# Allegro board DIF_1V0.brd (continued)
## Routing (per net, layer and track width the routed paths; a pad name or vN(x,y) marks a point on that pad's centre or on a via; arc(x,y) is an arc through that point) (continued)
/BUTTON_LOW: length 3
  TOP w0.152: R7.1 105.94,9.55 SW1.1
CCLK: length 22.1
  TOP w0.152: U5.16 v2(87.71,37.95) ; U3.L12 v1(90.62,54.25)
  ART2 w0.152: v1(90.62,54.25) 90.93,53.93 90.93,41.35 87.71,38.13 v2(87.71,37.95)
DONE: length 13.1
  TOP w0.152: v2(105.51,56.08) 104.8,55.37 D9.2 104.72,55.19 94.64,55.19 94.15,55.68 U3.G11
  BOTTOM w0.152: R44.1 104.8,56.08 v2(105.51,56.08)
FIFOADR0: length 34.1
  TOP w0.152: U12.44 67.61,22.85 67.61,24.49 66.95,25.15 66.95,32.92 75.01,40.97 v2(75.01,42.44) ; U3.V18 v1(82.69,48.25)
  ART2 w0.152: v1(82.69,48.25) 82.14,47.7 80.11,47.7 75.01,42.6 v2(75.01,42.44)
FIFOADR1: length 30.6
  TOP w0.152: U12.45 67.02,24.24 66.47,24.79 66.47,33.43 73.51,40.46 73.51,42.11 76.56,45.16 79.63,45.16 80.15,45.68 U3.AA21
FLASH_CS_B: length 29.9
  TOP w0.152: U3.T19 85.72,47.14 v2(85.75,47.14) ; v2(94.82,26.19) 95.33,25.68 U5.7
  BOTTOM w0.152: v2(94.82,26.19) 94.18,26.82 R37.1 94.69,27.51 94.69,36.86 92.15,39.4 89.18,39.4 85.57,43 85.57,44.48 85.29,44.75 85.29,46.69 v2(85.75,47.14)
FLASH_DQ0: length 11.2
  TOP w0.152: U3.P22 87.15,43.73 88.98,41.91 U5.15
FLASH_DQ1: length 27
  TOP w0.152: U3.R22 v1(86.15,44.04) ; v2(92.68,41.25) 97.23,36.7 97.23,32.8 96.6,32.16 96.6,28.25 96.7,28.15 96.7,27.73 96.6,27.63 U5.8
  BOTTOM w0.152: v2(92.68,41.25) 88.94,41.25 v1(86.15,44.04)
FLASH_DQ2: length 17.7
  TOP w0.152: v2(95.73,35.99) 96.6,35.13 U5.9 ; v2(88.39,41) 86.64,42.75 86.64,45.21 87.14,45.71 U3.P21
  BOTTOM w0.152: v2(88.39,41) 89.08,40.31 92.25,40.31 R36.1 95.73,36.83 v2(95.73,35.99)
FLASH_DQ3: length 23.3
  TOP w0.152: U5.1 87.71,25.81 86.46,27.05 R35.1 86.72,28.12 86.72,39.6 85.67,40.64 85.67,45.24 86.15,45.71 U3.R21
FPGA_LED1: length 33
  TOP w0.152: TP1.1 117.2,24.38 107.14,34.44 107.14,41.58 102.01,46.71 U3.A20
  TOP w0.203: R11.1 TP1.1
FPGA_LED2: length 29.8
  TOP w0.152: U3.C22 98.15,44.42 106.35,36.22 106.35,32.97 115.11,24.21 TP2.1
  TOP w0.203: R12.1 TP2.1
FPGA_LED3: length 30.4
  TOP w0.152: U3.D21 97.15,45.65 97.66,45.14 97.66,43.92 105.31,36.27 105.31,32.44 113.03,24.71 TP3.1
  TOP w0.203: R13.1 TP3.1
FPGA_LED4: length 29.9
  TOP w0.152: U3.E21 96.15,45.68 96.67,45.16 96.67,43.87 104.01,36.53 104.01,31.7 110.95,24.77 TP4.1
  TOP w0.203: R14.1 TP4.1
FPGA_LED5: length 28.1
  TOP w0.152: TP5.1 108.86,24.66 102.49,31.04 102.49,37.03 96.15,43.37 U3.E22
  TOP w0.203: R15.1 TP5.1
FPGA_LED6: length 29.6
  TOP w0.152: U3.F20 95.63,46.23 95.63,42.95 101.12,37.47 101.12,30.78 104.01,27.89 104.01,27.86 106.78,25.1 TP6.1
  TOP w0.203: R16.1 TP6.1
FPGA_LED7: length 28.6
  TOP w0.152: TP7.1 104.7,25.55 102.08,28.17 101.4,28.17 99.8,29.77 99.8,37.82 94.67,42.95 94.67,44.96 94.15,45.47 U3.G21
  TOP w0.203: R17.1 TP7.1
FPGA_LED8: length 26.3
  TOP w0.152: U3.G22 94.15,42.35 98.37,38.13 98.37,29.44 102.62,25.2 TP8.1
  TOP w0.203: R18.1 TP8.1
GTP0_RD+: length 32.3
  TOP w0.152: 106.5,57.43 C126.1 107.07,57.43 107.89,58.26 121.77,58.26 132.17,47.86 132.17,47.28 131.93,47.04 DU1.13
GTP0_RD-: length 32.7
  TOP w0.152: DU1.12 132.72,47.07 132.47,47.31 132.47,47.99 121.9,58.56 107.89,58.56 107.24,59.21 C120.1 106.5,59.21
GTP0_TD+: length 33.8
  TOP w0.152: DU1.18 127.91,47.07 127.67,47.31 127.67,47.99 123.74,51.92 109.7,51.92 v2(109.41,52.21) ; v2(107.35,60.25) 107.35,60.85 R67.2 107.8,61.29 C127.2
  BOTTOM w0.152: v2(109.41,52.21) 107.01,54.61 107.01,59.9 v2(107.35,60.25)
GTP0_TD-: length 34.2
  TOP w0.152: C133.2 105.77,62.61 105.94,62.43 105.94,61.32 R67.1 106.41,60.85 v2(106.41,60.25) ; v2(108.47,52.21) 109.07,51.61 123.61,51.61 127.37,47.86 127.37,47.31 127.13,47.07 DU1.19
  BOTTOM w0.152: v2(106.41,60.25) 106.71,59.96 106.71,53.98 v2(108.47,52.21)
GTP0_TX_DETECT: length 20.9
  TOP w0.152: D13.1 117.88,43.33 v2(119.86,41.35)
  TOP w0.203: v2(130.68,36.02) 130.68,37.74 DU1.6
  ART2 w0.152: v2(130.68,36.02) 130.07,35.41 123.9,35.41 119.86,39.45 v2(119.86,41.35)
  BOTTOM w0.203: DR3.1 v2(130.68,36.02)
IN_DATA_1+: length 29.2
  TOP w0.152: U8.6 32.39,7.45 v2(32.84,7.9)
  TOP w0.203: U8.6 32.36,7.27 32.36,8.72 39.22,15.57 45.8,15.57 49.38,19.15 U11.2 ; U8.18 v2(33.14,5.16)
  BOTTOM w0.152: v2(33.14,5.16) 32.84,5.46 v2(32.84,7.9)
IN_DATA_1-: length 24.3
  TOP w0.152: U8.7 32.64,6.49 U8.19
  TOP w0.203: U8.7 33.39,8.09 40.21,14.91 46.58,14.91 49.56,17.88 U11.1
IN_DATA_5+: length 26.7
  TOP w0.152: v2(49.3,11.1) 47.08,8.88 U9.2 ; v2(52.02,5.16) 51.83,5.34 U9.14 ; v2(51.21,23.63) U11.6
  BOTTOM w0.152: v2(52.02,5.16) 52.02,8.38 v2(49.3,11.1) 49.3,21.73 v2(51.21,23.63)
IN_DATA_5-: length 26.5
  TOP w0.152: v2(49.3,10.24) 47.58,8.52 U9.3 ; U11.7 50.62,24.92 v2(50.62,24.91) ; v2(51.13,5.13) 51.33,5.33 U9.15
  ART2 w0.152: v2(49.3,10.24) 49.81,10.74 49.81,24.09 v2(50.62,24.91)
  BOTTOM w0.152: v2(51.13,5.13) 51.13,8.41 v2(49.3,10.24)
IN_DATA_6+: length 34.3
  TOP w0.152: v2(46.53,25.5) U11.10 ; U9.23 47.33,5.24 v2(47.13,5.04) ; v2(47.13,13.84) 47.64,14.35 48.31,14.35 52.08,10.58 U9.11
  BOTTOM w0.152: v2(47.13,5.04) v2(47.13,13.84) 47.13,24.9 v2(46.53,25.5)
IN_DATA_6-: length 34.4
  TOP w0.152: U9.22 47.83,5.2 v2(48.03,5) ; v2(48.01,13.74) 51.58,10.17 U9.10 ; v2(46.81,26.75) 44.04,26.75 U11.9
  BOTTOM w0.152: v2(46.81,26.75) 48.41,25.15 48.41,14.15 v2(48.01,13.74) 48.03,13.72 v2(48.03,5)
IN_MONITOR: length 31.3
  TOP w0.152: U3.K2 v1(91.62,65.18)
  BOTTOM w0.152: v1(91.62,65.18) 91.62,72.75 106.17,87.3 R121.1
IN_TX_HV: length 53.9
  TOP w0.152: U6.4 33,79.67 42.9,69.77 60.55,69.77 67.94,62.38 75.67,62.38 76.34,61.71 U3.AB5
INIT_B: length 16.3
  TOP w0.152: v2(72.62,58.5) 71.96,58.5 D10.1 ; U3.U12 v2(83.69,55.17)
  BOTTOM w0.152: v2(83.69,55.17) 77.47,55.17 74.52,58.12 73.05,58.12 72.67,58.5 v2(72.62,58.5) 72.57,58.45 72.57,58.01 R45.1
IO_PRE_2.5_1: length 31.4
  TOP w0.102: U3.A1 99.86,65.71 99.75,65.81 99.75,70.97 115.85,87.06 115.85,87.95 115.96,88.06 v1(115.96,88.35)
  BOTTOM w0.102: R137.1 115.96,89.34 v1(115.96,88.35)
IO_PRE_2.5_2: length 31.4
  TOP w0.102: U3.B1 99.45,65.71 99.55,65.81 99.55,71.05 115.65,87.15 115.65,87.95 115.53,88.06 v1(115.53,88.35)
  BOTTOM w0.102: v1(115.53,88.35) 115.53,89.19 R139.1
IO_PRE_2.5_3: length 32.2
  TOP w0.102: U3.C2 98.45,64.71 98.55,64.81 98.55,72.04 114.25,87.74 114.25,88.65 113.64,89.26 R133.2
IO_PRE_2.5_4: length 32.2
  TOP w0.102: R135.2 115.06,89.26 114.45,88.65 114.45,87.66 98.75,71.96 98.75,64.81 98.86,64.71 U3.B2
IO_PRE_2.5_5: length 31.1
  TOP w0.102: v1(111.61,87.85) 111.61,87.56 111.72,87.44 111.72,86.42 96.55,71.25 96.55,65.81 96.45,65.71 U3.E1
  BOTTOM w0.102: R129.1 111.12,89.24 111.73,88.63 111.73,88.14 111.61,88.01 v1(111.61,87.85)
IO_PRE_2.5_6: length 31.1
  TOP w0.102: U3.D1 96.86,65.71 96.75,65.81 96.75,71.17 111.93,86.34 111.93,87.44 112.04,87.56 v1(112.04,87.85)
  BOTTOM w0.102: v1(112.04,87.85) 112.04,88.04 111.94,88.14 111.94,88.68 112.52,89.26 R131.1
IO_PRE_2.5_7: length 40.1
  TOP w0.152: U3.G3 94.15,63.72 v1(94.61,64.19)
  BOTTOM w0.152: v1(94.61,64.19) 94.64,64.19 95.17,64.72 95.17,69.32 111.33,85.47 116.76,85.47 120.14,88.85 R143.2
IO_PRE_2.5_8: length 41.9
  TOP w0.152: v1(95.63,63.17) 95.17,62.71 U3.F4 ; R149.1 v2(123.98,88.62)
  ART2 w0.152: v2(123.98,88.62) 112.7,77.34 107.77,77.34 96.19,65.76 96.19,63.73 v1(95.63,63.17)
IO_PRE_2.5_9: length 42.3
  TOP w0.152: U3.E2 96.18,64.71 v1(96.67,65.2)
  BOTTOM w0.152: v1(96.67,65.2) 96.67,68.55 111.02,82.91 119.79,82.91 125.22,88.34 R151.2
IO_PRE_2.5_10: length 43.9
  TOP w0.152: v1(96.62,64.16) 96.17,63.71 U3.E3 ; R153.1 v2(126.49,88.01)
  BOTTOM w0.152: v2(126.49,88.01) 119.2,80.72 110.26,80.72 97.18,67.64 97.18,64.67 96.67,64.16 v1(96.62,64.16)
IO_PRE_2.5_11: length 43.6
  TOP w0.152: U3.D2 97.15,64.72 v1(97.64,65.2)
  BOTTOM w0.152: R155.2 127.76,87.17 118.9,78.31 109.04,78.31 97.64,66.9 v1(97.64,65.2)
IO_PRE_3.3_1: length 31.8
  TOP w0.152: U3.R2 86.15,64.72 85.6,65.28 85.6,72.03 69.09,88.54 R160.2
IO_PRE_3.3_2: length 34.1
  TOP w0.152: v1(85.62,64.24) 86.15,63.71 U3.R3
  BOTTOM w0.152: v1(85.62,64.24) 85.62,72.39 R158.1
IO_PRE_3.3_3: length 34.8
  TOP w0.152: U3.R4 86.15,62.74 v1(85.65,63.25) ; R156.2 v2(66.55,88.16)
  ART2 w0.152: v2(66.55,88.16) 85.12,69.6 85.12,63.75 85.62,63.25 v1(85.65,63.25)
IO_PRE_3.3_4: length 36.6
  TOP w0.152: v1(84.66,63.17) 85.12,62.71 U3.T4
  ART2 w0.152: v1(84.66,63.17) 84.63,63.17 84.1,63.7 82.6,63.7 81.64,64.67 81.64,69.85 65.28,86.21 v2(65.28,88.27)
  BOTTOM w0.152: R154.1 v2(65.28,88.27)
IO_PRE_3.3_5: length 34.3
  TOP w0.152: R152.2 64.01,88.62 66.4,86.23 69.49,86.23 85.15,70.58 U3.T1
IO_PRE_3.3_6: length 38
  TOP w0.152: U3.T3 85.15,63.72 v1(84.66,64.21)
  BOTTOM w0.152: R150.1 62.74,89.46 67.41,84.79 71.12,84.79 84.15,71.75 84.15,64.69 84.63,64.21 v1(84.66,64.21)
IO_PRE_3.3_7: length 35
  TOP w0.102: 84.15,68.17 U3.U1
  TOP w0.152: R148.2 61.47,89.26 66.52,84.2 69.75,84.2 84.15,69.8 84.15,68.17
IO_PRE_3.3_8: length 39
  TOP w0.152: U3.U3 84.12,63.71 v1(83.64,64.19)
  BOTTOM w0.152: R146.1 60.2,89.56 67.49,82.27 71.7,82.27 83.64,70.33 v1(83.64,64.19)
IO_PRE_3.3_9: length 34
  TOP w0.152: R144.2 v2(58.93,88.29) ; U3.Y1 81.15,67.87 78.71,70.31 v2(76.91,70.31)
  ART2 w0.152: v2(76.91,70.31) v2(58.93,88.29)
IO_PRE_3.3_10: length 41.8
  TOP w0.152: U3.V3 v1(82.68,64.19)
  BOTTOM w0.152: v1(82.68,64.19) 82.68,68.99 71.58,80.09 65.68,80.09 55.5,90.27 R138.1
IO_PRE_3.3_11: length 54.3
  TOP w0.152: R111.2 38.61,89.15 52.63,75.13 64.52,75.13 71.12,68.53 79.63,68.53 80.67,67.49 80.67,65.2 81.15,64.72 U3.Y2
IO_PRE_3.3_12: length 54.1
  TOP w0.152: U3.V5 83.15,61.71 v1(82.65,62.2)
  ART2 w0.152: v1(76.17,64.46) 78.95,61.67 82.19,61.67 82.65,62.13 v1(82.65,62.2)
  BOTTOM w0.152: R118.1 42.42,89.84 57.15,75.11 66.83,75.11 76.17,65.77 v1(76.17,64.46)
IO_PRE_3.3_13: length 48.2
  TOP w0.152: U3.V4 83.14,62.71 v1(82.63,63.22)
  BOTTOM w0.152: R130.1 50.04,88.62 61.29,77.37 67.79,77.37 74.12,71.04 79.3,71.04 82.37,67.97 82.37,64.35 82.35,64.32 82.35,64.05 82.37,64.02 82.37,63.91 82.63,63.65 v1(82.63,63.22)
IO_PRE_3.3_14: length 44.5
  TOP w0.152: R132.2 51.31,89.15 58.06,82.4 69.39,82.4 82.65,69.14 82.65,65.21 U3.V2
IO_PRE_3.3_15: length 42.7
  TOP w0.152: U3.W1 82.35,65.9 82.35,68.28 78.74,71.88 v2(77.29,71.88)
  BOTTOM w0.152: R134.1 52.58,88.29 62.15,78.71 68.99,78.71 75.82,71.88 v2(77.29,71.88)
IO_SMA1: length 52.3
  TOP w0.152: U3.B21 99.59,46.15 v2(101.7,46.15) ; R19.2 125.68,21.79 108.08,39.4 v2(108.08,41.4)
  BOTTOM w0.152: v2(108.08,41.4) 106.45,41.4 v2(101.7,46.15)
IO_SMA2: length 48
  TOP w0.152: v2(101.04,45.69) 101.03,45.71 U3.A21 ; v2(109.45,38.81) 119.81,28.45 137.9,28.45 139.57,30.12 R26.2
  BOTTOM w0.152: v2(109.45,38.81) 107.92,38.81 v2(101.04,45.69)
IO_SMA3: length 44.1
  TOP w0.152: R30.2 v2(138.94,44.45) ; U3.B15 99.19,51.71 99.69,51.21 105.36,51.21 v2(105.51,51.05)
  ART2 w0.152: v2(105.51,51.05) 111.38,45.19 135.59,45.19 136.32,44.45 v2(138.94,44.45)
IO_SMA4: length 49.1
  TOP w0.102: v1(94.72,53.16) 94.17,53.71 U3.G13 ; v2(137.72,64.21) R28.2
  ART2 w0.102: v1(94.72,53.16) 94.72,53.24 95.2,53.72 124.51,53.72 135,64.21 v2(137.72,64.21)
IO_SMA5: length 45.8
  TOP w0.102: v1(94.67,51.21) 94.16,51.71 U3.G15 ; R32.2 138.23,53.52 v2(137.72,53.52)
  ART2 w0.102: v1(94.67,51.21) 94.69,51.21 96.16,52.68 113.13,52.68 113.69,52.12 130.56,52.12 131.8,53.37 137.57,53.37 v2(137.72,53.52)
M2: length 31
  TOP w0.152: J8.2 56.74,62.31 59.03,60.02 72.29,60.02 76.12,56.18 81.38,56.18 81.72,56.53 81.72,56.89 81.97,57.14 83.58,57.14 U3.U9
Net_18: length 0.7
  TOP w0.152: 87.15,49.71 v1(86.69,49.25)
Net_41: length 0.7
  TOP w0.152: 92.15,64.71 92.15,64.72 v1(92.61,65.18)
Net_42: length 0.7
  TOP w0.152: 90.15,63.71 v1(90.65,64.21)
Net_44: length 0.7
  TOP w0.152: v1(93.62,64.19) 93.15,63.71 93.15,63.71
Net_45: length 0.6
  TOP w0.152: 93.15,62.71 93.16,62.71 v1(93.6,63.14)
Net_46: length 0.7
  TOP w0.152: 95.15,63.71 95.18,63.71 v1(95.66,64.19)
Net_47: length 0.7
  TOP w0.152: v1(93.68,62.23) 93.16,61.71 93.15,61.71
Net_48: length 0.7
  TOP w0.152: v1(94.61,63.17) 94.16,62.71 94.15,62.71
OUT_CK_5N_1: length 3.5
  TOP w0.127: R81.2 84.68,88.58 84.71,88.56 R69.1 84.71,86.44 R70.1
OUT_CK_5P_1: length 3.6
  TOP w0.127: R68.2 83.19,86.33 R69.2 83.19,88.56 83.21,88.58 R79.2
OUT_CK_40N_1: length 3.6
  BOTTOM w0.127: R108.1 87.27,88.01 R115.1
  BOTTOM w0.152: R108.1 87.15,88.14 R97.1
OUT_CK_40P_1: length 3.6
  BOTTOM w0.127: R108.2 85.7,86.44 R95.2
  BOTTOM w0.152: R84.1 85.75,88.11 R108.2
OUT_DATA_2+: length 48.2
  TOP w0.203: U8.2 30.39,8.8 24.56,14.63 24.56,23.29 25.63,24.36 U10.2 31.04,24.36 v2(31.09,24.31) ; U8.14 35.14,4.89 v2(35.33,4.7)
  BOTTOM w0.203: v2(35.33,4.7) 34.19,5.84 34.19,21.21 v2(31.09,24.31)
OUT_DATA_2-: length 45.4
  TOP w0.203: U8.3 30.89,8.8 24.94,14.75 24.94,22.56 25.48,23.09 U10.3 31.22,23.09 v2(31.27,23.04) ; U8.15 34.64,4.9 v2(34.44,4.7)
  BOTTOM w0.203: v2(31.27,23.04) 33.63,20.68 33.63,5.51 v2(34.44,4.7)
OUT_DATA_3+: length 30.9
  TOP w0.152: v2(35.38,8.51) 35.38,7.25 U8.11
  TOP w0.203: U8.23 30.64,5.12 v2(30.56,5.03) ; U10.6 30.07,19.28 30.56,18.8 v2(30.56,18.68)
  ART2 w0.152: v2(30.56,18.68) 34.06,15.18 34.06,9.25 34.69,8.62 35.28,8.62 v2(35.38,8.51)
  BOTTOM w0.203: v2(30.56,18.68) v2(30.56,5.03)
OUT_DATA_3-: length 34.7
  TOP w0.152: v2(35.38,9.3) 35.38,9.28 34.85,8.74 34.85,7.28 U8.10
  TOP w0.203: v2(31.22,5.08) 31.14,5.15 U8.22 ; v2(31.22,20.45) 28.45,20.45 U10.5
  ART2 w0.152: v2(31.22,20.45) 31.72,20.45 35.38,16.79 v2(35.38,9.3)
  BOTTOM w0.203: v2(31.22,20.45) v2(31.22,5.08)
OUT_DATA_4+: length 20.2
  TOP w0.152: U10.10 35.56,18.03 v2(38.18,18.03) ; v2(49.08,8.31) U9.6 49.83,6.49 U9.18
  ART2 w0.152: v2(38.18,18.03) 39.35,18.03 v2(49.08,8.31)
OUT_DATA_4-: length 23.4
  TOP w0.152: U9.7 50.04,7.28 50.04,7.29 v2(49.68,7.65) ; v2(38.15,19.28) U10.11 ; U9.19 v2(49.33,5.18)
  ART2 w0.152: v2(38.15,19.28) 38.83,19.28 49.68,8.43 v2(49.68,7.65)
  BOTTOM w0.152: v2(49.33,5.18) 49.68,5.53 v2(49.68,7.65)
OUT_RAZ_CHN_N_1: length 4.7
  TOP w0.102: 94.21,87.93 94.21,87.93 94.11,87.82 94.11,86.94 R90.1 ; 94.21,87.93 R85.1 ; 94.21,87.93 94.11,88.04 94.11,88.65 94.72,89.26 R93.2
OUT_RAZ_CHN_P_1: length 4.9
  TOP w0.102: R102.2 93.24,89.26 93.9,88.6 93.9,88.04 93.8,87.93 ; R85.2 93.8,87.93 ; 93.8,87.93 93.9,87.83 93.9,87 93.19,86.28 R82.2
OUT_RX_HV: length 55.4
  TOP w0.152: U6.3 33.23,80.94 42.65,71.53 59.79,71.53 68.3,63.02 76.71,63.02 77.47,62.26 79.63,62.26 80.15,61.73 U3.AA5
OUT_TRIG_EXT_N_1: length 3.5
  BOTTOM w0.127: R76.1 92.38,86.41 R75.1 92.3,88.09 R101.1
OUT_TRIG_EXT_P_1: length 3.6
  BOTTOM w0.127: R74.2 90.73,86.36 90.86,86.49 R75.2 90.91,88.06 R89.1
OUT_VAL_EVT_N_1: length 4.2
  TOP w0.102: R88.2 89.84,89.74 89.2,89.1 89.2,88.57 89.81,87.96 R72.1
  TOP w0.127: R72.1 89.89,86.44 R73.1
OUT_VAL_EVT_P_1: length 4.1
  TOP w0.102: R72.2 89,88.6 89,89.08 88.37,89.71 R98.2
  TOP w0.127: R72.2 88.37,86.39 R71.2
PROGRAM_B: length 44.1
  TOP w0.152: v2(108.08,34.49) 108.13,34.54 R43.1 110.72,34.54 SW2.2 ; U3.N12 88.15,54.7 v1(87.63,54.18)
  BOTTOM w0.152: v2(108.08,34.49) 108.03,34.54 104.8,34.54 96.75,42.6 89.46,42.6 88.14,43.92 88.14,53.67 v1(87.63,54.18)
REFCLK+: length 6
  BOTTOM w0.102: C1.1 112.29,61.04 R1.1 113.77,61.52 114.05,61.8 116.36,61.8 116.56,61.59 O1.4
REFCLK-: length 5.8
  BOTTOM w0.102: O1.5 116.56,62.23 116.33,62 114.02,62 113.77,62.26 R1.2 112.62,62.56 C5.1
RESET#: length 32.3
  TOP w0.203: U12.49 64.47,22.8 v2(64.47,21.29)
  ART2 w0.203: U15.2 85.98,17.42 68.33,17.42 v2(64.47,21.29)
  BOTTOM w0.203: C115.1 87.62,21.62 R65.1 87.68,19.13 U15.2
RX_VCCP_0: length 11.5
  TOP w0.305: v3(129.9,43.89) 130.33,44.32 DU1.15
  BOTTOM w0.203: C130.1 131.93,46.18 C129.1
  BOTTOM w0.305: C130.1 131.6,45.97 129.9,44.27 v3(129.9,43.89) L5.1 129.18,43.38 C128.1
SCL: length 15.4
  TOP w0.203: v2(73.38,14.3) 73.38,12.92 U12.22 ; v2(75.51,11.46) U14.6 84.3,11.89 R63.1
  BOTTOM w0.203: v2(75.51,11.46) 73.38,13.59 v2(73.38,14.3)
SDA: length 13.8
  TOP w0.203: U12.23 74,11.95 75.08,10.87 81.92,10.87 U14.5 83.9,8.89 R64.1
SFP_RS0: length 8.2
  TOP w0.203: DU1.7 131.52,38.96 132.94,40.39 v2(135.69,40.39)
  BOTTOM w0.203: v2(135.69,40.39) 136.35,40.39 DR14.1 136.8,40.79 DR15.1
SFP_RS1: length 8.5
  TOP w0.203: v2(135.69,32.36) 133.12,34.92 DU1.9
  BOTTOM w0.203: DR12.1 DR13.1 v2(135.69,32.36)
TRG_EXT: length 14.3
  TOP w0.152: R22.2 113.45,53.71 U3.A13
TX_VCCP_0: length 13.3
  TOP w0.305: DU1.16 129.51,47.24 128.65,48.11 v3(128.65,48.67)
  BOTTOM w0.203: C122.1 L4.1
  BOTTOM w0.305: C121.1 126.19,52.71 C123.1 129.41,50.5 L4.1 129.54,49.56 v3(128.65,48.67)
USB_CLKOUT: length 44.1
  TOP w0.152: U3.Y18 v1(80.69,48.25)
  BOTTOM w0.152: R52.1 60.53,19.53 60.53,34.14 69.72,43.33 70.94,43.33 75.86,48.25 v1(80.69,48.25)
USB_FD0: length 34.7
  TOP w0.152: v2(80.39,38.13) 80.39,41.38 82.15,43.14 U3.W22
  TOP w0.203: U12.25 v2(75.27,21.15)
  BOTTOM w0.152: v2(80.39,38.13) 80.39,32.11 75.27,26.99 v2(75.27,21.15)
USB_FD1: length 36.6
  TOP w0.152: U3.T21 85.13,45.71 84.68,45.26 84.68,42.24 83.92,41.48 83.92,32.41 78,26.49 78,21.77 75.91,19.67 U12.26
USB_FD2: length 40.8
  TOP w0.152: U12.27 76.54,18.78 80.04,22.28 80.04,27.66 84.56,32.18 84.56,41.28 v2(84.66,41.38) ; U3.R17 v1(85.69,49.25)
  ART2 w0.152: v1(85.69,49.25) 85.69,49.19 85.14,48.64 85.14,46.43 84.66,45.95 v2(84.66,41.38)
USB_FD3: length 42
  TOP w0.152: U12.28 77.18,18.1 81.36,22.28 81.36,27.61 85.17,31.42 v2(85.17,40.74) ; U3.P16 v1(86.69,50.25)
  ART2 w0.152: v1(86.69,50.25) 86.64,50.25 86.16,49.76 86.16,44.86 85.65,44.35 85.65,41.16 85.23,40.74 v2(85.17,40.74)
USB_FD4: length 29.4
  TOP w0.152: U12.29 77.18,26.99 83.29,33.1 v2(83.29,39.19) ; U3.T18 v1(84.69,48.25)
  ART2 w0.152: v2(83.29,39.19) 83.29,46.51 83.57,46.79 83.95,46.79 84.69,47.53 v1(84.69,48.25)
USB_FD5: length 29.9
  TOP w0.152: v2(82.75,38.79) 82.75,33.22 76.54,27.01 U12.30 ; U3.R18 v1(85.69,48.25)
  BOTTOM w0.152: v2(82.75,38.79) 82.75,40.46 83.69,41.4 83.69,42.27 84.82,43.39 84.82,46.82 85.69,47.69 v1(85.69,48.25)
USB_FD6: length 26.3
  TOP w0.152: U12.31 75.91,27.42 82.25,33.76 82.25,39.98 82.45,40.18 82.45,41.73 83.67,42.95 83.67,45.26 84.11,45.71 U3.U21
USB_FD7: length 29.6
  TOP w0.152: U12.32 75.27,27.98 81.71,34.42 v2(81.71,40.64) ; U3.U18 v1(83.69,48.25)
  BOTTOM w0.152: v1(83.69,48.25) 83.69,48.23 83.16,47.7 83.16,42.09 v2(81.71,40.64)
USB_FD8: length 34.6
  TOP w0.152: U12.52 62.57,24.64 61.72,25.49 61.72,34.65 73.79,46.71 U3.AB20
USB_FD9: length 36.6
  TOP w0.152: U12.53 61.94,24.24 61.16,25.02 61.16,34.77 73.56,47.17 79.55,47.17 80.09,47.71 U3.AA19
USB_FD10: length 38.1
  TOP w0.152: U3.AA18 80.15,48.71 79.65,48.21 73.36,48.21 60.5,35.36 60.5,24.92 61.3,24.12 U12.54
USB_FD11: length 38
  TOP w0.152: U3.AB18 72.89,48.71 59.74,35.56 59.74,25.07 60.67,24.14 U12.55
USB_FD12: length 43.4
  TOP w0.152: v2(67.48,44.36) 59.03,35.92 59.03,25.12 60.03,24.12 U12.56 ; U3.V17 v1(82.69,49.25)
  BOTTOM w0.152: v2(67.48,44.36) 71.81,48.69 82.14,48.69 82.69,49.24 v1(82.69,49.25)
USB_FD13: length 56.7
  TOP w0.152: U3.W17 v1(81.69,49.25) ; U12.1 60.03,18.5 56.62,21.92 56.62,37.72 v2(64.5,45.61)
  BOTTOM w0.152: v2(64.5,45.61) 68.14,49.25 v1(81.69,49.25)
USB_FD14: length 57.9
  TOP w0.152: U3.U17 v1(83.69,49.25) ; v2(64.24,44.22) 57.68,37.67 57.68,22.05 60.67,19.06 U12.2
  ART2 w0.152: v1(83.69,49.25) 83.67,49.25 83.19,49.73 76.5,49.73 72.9,46.13 66.17,46.13 64.26,44.22 v2(64.24,44.22)
USB_FD15: length 58.9
  TOP w0.152: v2(66.65,44.75) 58.39,36.5 58.39,22.68 61.3,19.77 U12.3 ; U3.R16 v1(85.69,50.25)
  ART2 w0.152: v2(66.65,44.75) 67.01,45.11 72.92,45.11 76.53,48.72 83.95,48.72 84.1,48.87 84.1,49.71 84.64,50.25 v1(85.69,50.25)
USB_FLAGA: length 28.2
  TOP w0.152: U12.36 72.73,26.56 80.98,34.8 v2(80.98,41.1) ; U3.V20 v1(82.69,46.25)
  BOTTOM w0.152: v1(82.69,46.25) 82.69,46.24 82.17,45.72 82.17,42.29 v2(80.98,41.1)
USB_FLAGB: length 28.1
  TOP w0.152: v2(79.78,40.67) 79.78,34.49 72.31,27.03 72.31,24.52 72.1,24.31 U12.37 ; U3.W20 v1(81.69,46.25)
  BOTTOM w0.152: v2(79.78,40.67) 79.78,41.53 81.13,42.88 81.13,45.69 81.68,46.25 v1(81.69,46.25)
USB_FLAGC: length 23.7
  TOP w0.152: R55.2 71.48,27.1 79.15,34.77 79.15,41.02 81.69,43.56 81.69,45.29 82.11,45.71 U3.W21
USB_FLAGD/SLCS#: length 33.6
  TOP w0.152: v2(71.98,41.61) 65.13,34.75 65.13,24.74 65.75,24.12 U12.47 ; U3.Y19 v1(80.69,47.25)
  BOTTOM w0.152: v2(71.98,41.61) 76.07,45.69 79.15,45.69 80.69,47.24 v1(80.69,47.25)
USB_IFCLK: length 35.6
  TOP w0.152: U3.Y22 81.15,43.69 78.41,40.94 v2(78.41,39.62)
  TOP w0.203: U12.20 v2(72.1,21.12)
  BOTTOM w0.152: v2(72.1,21.12) 72.1,29.63 78.41,35.94 v2(78.41,39.62)
USB_PKTEND: length 30.7
  TOP w0.152: U3.AB21 75.61,45.71 72.69,42.8 72.69,41.02 65.86,34.19 65.86,24.77 66.38,24.24 U12.46
USB_SLOE: length 23.7
  TOP w0.152: R58.2 69.85,27.03 77.7,34.87 77.7,40.92 80.62,43.84 80.62,45.21 81.12,45.71 U3.Y21
USB_SLRD: length 37.9
  TOP w0.152: v2(77.38,41.69) 79.15,43.47 U3.AB22
  TOP w0.203: U12.8 64.48,19.04 v2(66.42,20.98)
  BOTTOM w0.152: v2(77.38,41.69) 75.87,40.18 75.87,35 66.42,25.55 v2(66.42,20.98)
USB_SLWR: length 41.6
  TOP w0.152: U3.W19 v1(81.69,47.25)
  BOTTOM w0.152: R59.2 65.65,17.49 65.65,37.15 75.64,47.14 79.53,47.14 80.01,47.63 81.31,47.63 v1(81.69,47.25)
USB_WAKEUP: length 29.9
  TOP w0.152: U3.AA20 80.14,46.71 79.63,46.2 74.47,46.2 64.26,35.99 64.26,28.83 63.2,27.76 R56.1
USB_WU2: length 28.3
  TOP w0.152: v2(77.19,43.74) 75.87,42.42 75.87,34.29 R57.1 ; U3.V19 v1(82.69,47.25)
  ART2 w0.152: v1(82.69,47.25) 82.69,47.23 82.14,46.69 80.14,46.69 v2(77.19,43.74)
WU: length 7.1
  TOP w0.203: J13.2 62.28,28.32 62.28,26.21 R56.2 63.2,22.82 U12.51
WU2_S: length 7.2
  TOP w0.203: J14.2 67.49,28.55 67.49,26.01 R57.2 68.29,25.18 U12.43
XTALIN: length 9.9
  TOP w0.203: U12.12 67.02,7.66 Y1.1
  BOTTOM w0.203: C107.2 66.7,7.34 Y1.1
XTALOUT: length 12.5
  TOP w0.203: U12.11 66.38,10.07 62.61,6.3 Y1.2
  BOTTOM w0.203: C106.2 61.95,7.67 Y1.2
N00327: length 5.3
  TOP w0.203: C102.1 32.61,72.14 U6.10
  TOP w0.305: U6.10 32.69,72.06 R48.1
N00500: length 9.5
  TOP w0.305: U6.16 17.73,79.95 R49.2
N00677: length 1.5
  TOP w0.305: R50.2 13.88,84.98 U7.3
N00715: length 5.6
  TOP w0.152: v3(13.11,81.53) 12.88,81.76 12.88,83.24 12.38,83.73 U7.4
  TOP w0.305: U7.4 11.93,85.1 R51.2
  BOTTOM w0.305: C105.1 v3(13.11,81.53)
N12323: length 6.4
  TOP w0.203: J7.4 53.52,59.64 R38.1
N12327: length 33
  TOP w0.152: v2(76.95,54.57) 78.33,53.19 84.68,53.19 85.15,53.66 U3.T13 ; v2(74.37,57.15) 73.63,57.89 56.85,57.89 R38.2
  BOTTOM w0.152: v2(76.95,54.57) v2(74.37,57.15)
N12331: length 29.1
  TOP w0.152: U3.V12 82.67,55.19 75.49,55.19 74.75,55.93 56.21,55.93 R39.2
N12335: length 29.9
  TOP w0.152: v2(76.17,53.95) 75.54,54.58 72.8,54.58 72.78,54.56 72.36,54.56 72.33,54.58 R40.2 ; v2(83.68,54.17) 84.14,53.71 U3.U13
  BOTTOM w0.152: v2(83.68,54.17) 83.65,54.17 83.19,53.7 76.43,53.7 v2(76.17,53.95)
N12339: length 31.8
  TOP w0.152: v2(75.92,52.68) 55.7,52.68 R41.2 ; U3.R13 86.15,53.69 v2(85.65,53.19)
  BOTTOM w0.152: v2(85.65,53.19) 85.42,52.96 76.2,52.96 v2(75.92,52.68)
N12343: length 6.4
  TOP w0.203: R39.1 47.17,57.07 J7.6
N12347: length 6.4
  TOP w0.203: R40.1 47.17,54.58 J7.8
N12351: length 6.4
  TOP w0.203: R41.1 47.17,52.04 J7.10
N12485: length 49.7
  TOP w0.152: U3.AB17 66.3,49.71 55.4,38.81 55.4,22.33 53.49,20.42 U11.3
N12489: length 49.7
  TOP w0.152: U11.5 53.52,22.96 54.66,24.1 54.66,39.95 64.92,50.22 79.68,50.22 80.15,50.69 U3.AA16
N12493: length 51.7
  TOP w0.152: U11.11 46.18,24.23 47.73,25.78 47.73,35.38 63.05,50.71 U3.AB16
N12742: length 63
  TOP w0.152: U3.AA14 80.14,52.71 v1(79.58,52.15) ; v2(51.99,47.9) 29.72,25.63 U10.1
  BOTTOM w0.152: v1(79.58,52.15) 79.58,52.12 79.02,51.56 55.65,51.56 v2(51.99,47.9)
N12746: length 69.4
  TOP w0.152: U10.7 30.99,18.01 32.46,19.48 32.46,27.36 56.82,51.71 U3.AB15
N12750: length 65.5
  TOP w0.152: U10.9 37.8,16.74 39.27,18.21 39.27,29.03 61.44,51.21 79.68,51.21 80.15,51.68 U3.AA15
N13183: length 2.7
  TOP w0.152: v2(108.64,54.43) 107.95,55.12 D9.1
  BOTTOM w0.152: v2(108.64,54.43) R47.2
N13221: length 1.8
  TOP w0.152: D10.2 R46.1
N15768: length 37.8
  TOP w0.152: v2(105.51,52.07) 104.87,52.71 U3.A14
  TOP w0.203: DU1.3 128.3,37.8 v2(128.3,39.62)
  BOTTOM w0.152: v2(105.51,52.07) 110.69,46.89 112.27,46.89 119.81,39.34 126.7,39.34 DR2.1
  BOTTOM w0.203: DR16.1 127.46,38.79 v2(128.3,39.62) 127.84,40.08 DR2.1
N15772: length 53.1
  TOP w0.152: DU1.2 127.53,38.91 126.92,39.52 113.87,39.52 103.2,50.19 99.67,50.19 U3.B16 ; v2(120.14,44.04) 117.93,46.25 D12.1
  TOP w0.203: v2(127.53,35.99) DU1.2
  ART2 w0.152: v2(120.14,44.04) 120.78,43.41 120.78,40.61 122.12,39.27 124.59,39.27 127.53,36.32 v2(127.53,35.99)
  BOTTOM w0.203: DR1.1 v2(127.53,35.99)
N15776: length 38.7
  TOP w0.152: U3.B17 99.18,49.71 99.75,49.15 102.31,49.15 113.61,37.85 117.32,37.85 119.91,35.26 128.3,35.26 v2(129.08,36.04)
  TOP w0.203: v2(129.08,36.04) 129.08,37.74 DU1.4
  BOTTOM w0.203: DR5.1 v2(129.08,36.04)
N15834: length 38.9
  TOP w0.152: U3.B13 99.15,53.45 99.44,53.16 105.49,53.16 108.38,50.27 117.73,50.27 124.74,43.26 125.96,43.26 128.85,40.36 v2(128.93,40.36)
  TOP w0.203: DU1.5 129.95,37.8 v2(129.95,39.29)
  BOTTOM w0.203: v2(129.95,39.29) DR6.1 129.21,40.08 v2(128.93,40.36)
N15838: length 60.4
  TOP w0.152: U3.A18 101.45,48.71 108.25,41.91 108.29,41.91 108.58,41.61 108.58,41.58 113.51,36.65 116.92,36.65 118.92,34.65 130.91,34.65 v2(132.28,36.02) ; D14.1 v2(119.05,41.35)
  TOP w0.203: DU1.8 132.28,37.74 v2(132.28,36.02)
  ART2 w0.152: v2(132.28,36.02) 130.99,34.72 122.71,34.72 119.05,38.38 v2(119.05,41.35)
  BOTTOM w0.203: DR4.1 v2(132.28,36.02)
N16065: length 7
  TOP w0.102: R66.1 103.12,57.58 102.59,58.11 100.45,58.11 99.86,58.11 99.64,58.33 99.64,58.52 99.45,58.71 U3.B8
  TOP w0.152: R66.1 105.33,57.58 C126.2
N16069: length 6.6
  TOP w0.102: R66.2 103.39,59.11 102.6,58.32 99.94,58.32 99.84,58.42 99.84,58.61 99.94,58.71 U3.A8
  TOP w0.152: C120.2 105.38,59.11 R66.2
N16073: length 10.3
  TOP w0.102: 107.8,64.14 107.8,64.16 107.7,64.16 106.58,65.28 103.01,65.28 101.04,63.31 100.36,63.31 99.63,63.31 99.15,62.83 U3.B4
N16077: length 9
  TOP w0.102: C133.1 105.89,64.16 106.56,64.83 106.56,65.01 106.49,65.07 103.1,65.07 101.13,63.1 100.45,63.1 100.13,63.1 100.03,63 100.03,62.84 U3.A4
N17024: length 12.3
  TOP w0.152: v1(94.72,58.12) 95.15,58.55 U3.F8
  ART2 w0.152: v2(103.66,62.48) 102.13,60.96 99.72,60.96 98.4,59.64 96.24,59.64 v1(94.72,58.12)
  BOTTOM w0.152: v2(103.66,62.48) 103.66,61.72 R34.2
N26834: length 33
  TOP w0.152: v1(88.7,63.2) 88.21,62.71 U3.N4 ; R114.2 v2(102.36,88.72)
  ART2 w0.152: v2(91.34,76.81) 89.64,75.11 89.64,65.64 89.33,65.34 89.33,64.37 89.31,64.35 89.31,63.86 88.7,63.25 v1(88.7,63.2)
  BOTTOM w0.152: v2(91.34,76.81) 91.34,77.7 v2(102.36,88.72)
N27061: length 34.1
  TOP w0.152: v1(89.66,62.18) 89.19,61.71 U3.M5
  ART2 w0.152: v2(91.36,74.93) 90.14,73.71 90.14,62.71 89.66,62.23 v1(89.66,62.18)
  BOTTOM w0.152: R117.1 103.63,87.58 91.36,75.31 v2(91.36,74.93)
N27703: length 31
  TOP w0.152: R110.2 v2(99.82,88.87) ; v1(88.62,64.19) 88.15,63.72 U3.N3
  BOTTOM w0.152: v1(88.62,64.19) 88.65,64.19 89.15,64.69 89.15,73.58 90.09,74.52 90.09,78.41 99.82,88.14 v2(99.82,88.87)
N27930: length 30.1
  TOP w0.152: v1(89.66,65.2) 89.17,64.71 U3.M2
  BOTTOM w0.152: v1(89.66,65.2) 89.66,73.28 90.83,74.45 90.83,78.21 101.09,88.47 R112.1
N28287: length 29.4
  TOP w0.152: U3.N2 88.15,64.73 88.62,65.2 88.62,73.76 v2(88.77,73.91)
  BOTTOM w0.152: v2(88.77,73.91) 89.1,74.24 89.1,78.11 98.55,87.55 R107.1
N29233: length 33.9
  TOP w0.152: U3.K4 91.16,62.71 v1(91.64,63.2) ; R123.2 v2(107.44,88.87)
  ART2 w0.152: v1(91.64,63.2) 92.18,63.73 92.18,68.61 93.17,69.6 93.17,73.33 v2(97.38,77.55)
  BOTTOM w0.152: v2(107.44,88.87) 107.44,87.6 v2(97.38,77.55)
N29237: length 33.4
  TOP w0.152: U3.K3 91.17,63.71 v1(91.64,64.19)
  BOTTOM w0.152: R125.1 108.69,87.33 92.15,70.79 92.15,64.69 v1(91.64,64.19)
N31078: length 20.6
  TOP w0.127: R71.1 88.27,84.73 89.05,83.95 89.05,76.07 91.54,73.59 91.54,66.1 U3.K1
N31082: length 20.5
  TOP w0.127: R73.2 89.28,83.95 89.28,76.17 91.77,73.68 91.77,66.1 U3.J1
N31695: length 20.9
  TOP w0.127: R68.1 83.26,84.81 83.81,84.26 83.81,79.04 86.61,76.23 86.61,66.17 U3.R1
N31699: length 20.8
  TOP w0.127: U3.P1 86.84,66.02 86.84,76.33 84.04,79.13 84.04,84.24 84.61,84.81 R70.2
N31992: length 20.9
  TOP w0.127: v1(86.21,83.28) 86.21,82.97 86.31,82.87 86.31,77.72 89.54,74.5 89.54,66.1 U3.M1
  BOTTOM w0.127: v1(86.21,83.28) 86.21,83.67 85.57,84.3 R95.1
N31996: length 20.9
  TOP w0.127: v1(86.64,83.28) 86.64,82.97 86.54,82.87 86.54,77.82 89.77,74.59 89.77,66.1 U3.L1
  BOTTOM w0.127: R115.2 87.27,84.3 86.64,83.67 v1(86.64,83.28)
N32289: length 22
  TOP w0.102: U3.H2 93.45,64.71 93.55,64.81 93.55,64.96 93.55,64.96 93.55,76 91.45,78.09 91.45,82.6 91.27,82.78 v2(91.27,83.15)
  BOTTOM w0.127: v2(91.27,83.15) 91.27,83.39 91.44,83.55 91.44,84.54 91.15,84.84 R74.1
N32293: length 22.1
  TOP w0.102: U3.G2 93.86,64.71 93.75,64.81 93.75,65.04 93.75,65.04 93.75,76.12 91.68,78.19 91.68,82.6 91.86,82.78 v2(91.86,83.15)
  BOTTOM w0.127: R76.2 91.97,84.84 91.67,84.53 91.67,83.54 91.86,83.35 v2(91.86,83.15)
N33117: length 20
  TOP w0.102: R82.1 93.66,84.16 93.71,84.16 93.81,84.06 93.81,77.94 94.55,77.2 94.55,65.81 94.45,65.71 U3.G1
N33121: length 20.1
  TOP w0.102: R90.2 94.68,84.76 94.02,84.09 94.02,78.02 94.75,77.29 94.75,65.81 94.86,65.71 U3.F1
N33886: length 31.6
  TOP w0.152: v1(87.58,63.14) 87.15,62.72 U3.P4 ; R105.2 v2(97.28,88.72)
  BOTTOM w0.152: v2(97.28,88.72) 97.28,87.1 88.27,78.08 88.27,67.56 88.57,67.26 88.57,66.17 88.14,65.74 88.14,63.7 v1(87.58,63.14)
N33890: length 28.8
  TOP w0.152: v2(87.6,74.3) 87.6,65.18 87.15,64.72 U3.P2
  BOTTOM w0.152: v2(87.6,74.3) 87.6,78.18 96.01,86.59 R94.1
N34550: length 64.1
  TOP w0.152: v1(80.67,60.2) 81.15,59.72 U3.Y7
  BOTTOM w0.152: R91.1 31.67,88.32 34.29,88.32 50.75,71.86 64.41,71.86 75.59,60.68 80.19,60.68 v1(80.67,60.2)
N34554: length 64.6
  TOP w0.152: U3.AA4 80.15,62.72 79.71,63.17 77.72,63.17 77.29,63.6 69.93,63.6 61.26,72.26 43.28,72.26 40.23,75.31 40.23,78.44 29.26,89.41 R100.2
N36552: length 60.4
  TOP w0.152: U3.W5 82.15,61.74 v1(81.66,62.23)
  BOTTOM w0.152: R96.1 35.08,90.27 51.71,73.63 65.79,73.63 73.81,65.61 73.81,64.19 76.25,61.75 81.15,61.75 81.64,62.23 v1(81.66,62.23)
N36779: length 53.6
  TOP w0.152: U3.AB2 76.86,67.01 71.25,67.01 63.8,74.45 50.62,74.45 36.07,89 R106.2
N37008: length 58.3
  TOP w0.152: U3.W6 82.14,60.71 v1(81.58,61.26)
  ART2 w0.152: v2(37.36,89.05) 63.88,62.53 74.8,62.53 76.66,60.68 81.05,60.68 81.58,61.21 v1(81.58,61.26)
  BOTTOM w0.152: R109.1 v2(37.36,89.05)
N38396: length 57.2
  TOP w0.152: U3.AA3 80.13,63.71 79.68,64.16 78.49,64.16 76.66,65.99 70.94,65.99 63.27,73.66 49.3,73.66 R104.2
N38400: length 61.4
  TOP w0.152: v1(80.62,61.24) 81.15,60.71 U3.Y6
  BOTTOM w0.152: R103.1 33.53,90.27 51.03,72.77 64.97,72.77 72.34,65.41 72.34,64.95 76.05,61.24 v1(80.62,61.24)
N38404: length 59
  TOP w0.152: R92.2 30.99,89.1 47.22,72.87 62.69,72.87 62.84,72.72 62.84,72.67 70.36,65.15 76.58,65.15 78.02,63.71 U3.AB3
N38635: length 68.1
  TOP w0.152: v1(81.66,60.2) 82.15,59.71 U3.W7
  BOTTOM w0.152: v1(81.66,60.2) 81.64,60.2 81.13,59.69 74.75,59.69 63.5,70.94 50.22,70.94 33.53,87.63 29.82,87.63 R99.1
N38992: length 74.8
  TOP w0.152: R87.2 25.88,74.57 31.62,68.83 60.66,68.83 67.72,61.77 74.75,61.77 75.34,61.19 79.68,61.19 80.15,60.72 U3.AA6
N39253: length 76.8
  TOP w0.152: R83.2 23.37,75.26 30.48,68.15 59.77,68.15 66.83,61.09 73.15,61.09 75.53,58.71 U3.AB8
N39482: length 72.1
  TOP w0.152: U3.Y8 81.14,58.71 v1(80.64,59.21)
  BOTTOM w0.152: v1(80.64,59.21) 74.32,59.21 69.9,63.63 67.79,63.63 61.7,69.72 49.5,69.72 32.69,86.54 25.86,86.54 24.43,87.96 24.43,87.96 24.13,88.26 24.13,88.27 R80.1
N39711: length 81.7
  TOP w0.152: R78.2 20.8,75.31 28.91,67.21 59.49,67.21 66.27,60.43 72.95,60.43 75.18,58.19 80.67,58.19 U3.Y9
N39940: length 77.5
  TOP w0.152: U3.W9 82.14,57.71 v1(81.69,58.17)
  BOTTOM w0.152: R77.1 24.41,85.42 32.16,85.42 37.47,80.11 37.47,77.67 47.35,67.79 59.92,67.79 67.11,60.6 71.81,60.6 73.71,58.7 81.18,58.7 81.69,58.19 v1(81.69,58.17)
N40729: length 53.5
  TOP w0.152: v1(80.67,63.2) 81.15,62.71 U3.Y4
  BOTTOM w0.152: R113.1 55.52,74.63 66.19,74.63 74.9,65.91 74.9,64.49 76.2,63.2 v1(80.67,63.2)
N40733: length 55.2
  TOP w0.152: R116.2 v2(41.15,88.19) ; v1(83.64,62.18) 84.11,61.71 U3.U5
  ART2 w0.152: v2(41.15,88.19) 42.95,88.19 65.91,65.23 77.65,65.23 80.14,62.74 83.13,62.74 83.64,62.23 v1(83.64,62.18)
N41303: length 45.4
  TOP w0.152: U3.W2 82.15,64.74 81.64,65.25 81.64,68.22 78.82,71.04 76.25,71.04 68.86,78.44 59.74,78.44 R128.2
N42028: length 43.3
  TOP w0.152: v2(78.31,67.72) 79.15,66.87 U3.AB1
  ART2 w0.152: v2(78.31,67.72) 77.67,68.35 68.15,68.35 v2(47.5,89)
  BOTTOM w0.152: R126.1 v2(47.5,89)
N42251: length 46
  TOP w0.152: v1(80.16,67.31) 80.16,65.72 U3.AA1 ; R124.2 v2(46.23,88.21)
  ART2 w0.152: v1(80.16,67.31) 80.01,67.16 66.45,67.16 46.23,87.38 v2(46.23,88.21)
N42476: length 50.2
  TOP w0.152: U3.Y3 81.12,63.71 v1(80.62,64.21) ; v2(76.05,69.16) 75.9,69.16 73.99,71.07 70.61,71.07 64.92,76.76 56.31,76.76 R120.2
  BOTTOM w0.152: v2(76.05,69.16) 79.15,69.16 80.62,67.69 v1(80.62,64.21)
N42480: length 51.2
  TOP w0.152: v1(81.61,63.25) 82.15,62.71 U3.W4
  BOTTOM w0.152: R122.1 58.88,76.35 66.62,76.35 73.25,69.72 79.58,69.72 81.03,68.28 81.03,63.86 81.61,63.27 v1(81.61,63.25)
N63573: length 16.8
  TOP w0.102: v1(95.89,61.21) 95.89,60.81 95.99,60.71 U3.E6
  BOTTOM w0.102: C5.2 109.4,62.89 R2.2 109.07,62.74 107.16,60.83 95.99,60.83 95.89,60.93 v1(95.89,61.21)
N64906: length 7.3
  TOP w0.203: C103.1 36.83,74.37 R48.2 36.83,69.95 TP10.1 ; R145.1 v2(121.41,88.8)
  BOTTOM w0.203: R147.2 v2(122.66,88.72)
N64910: length 56.9
  TOP w0.152: C104.1 16.1,88.65 v2(15.27,88.65)
  TOP w0.305: C104.1 16.15,87.3 R49.1 15.67,86.72 R50.1
  BOTTOM w0.102: 14.38,90.32 14.38,95.78 16.74,98.15 R142.1
  BOTTOM w0.152: 14.38,90.32 14.38,89.53 v2(15.27,88.65)
N65349: length 17.1
  TOP w0.102: v1(95.48,61.21) 95.48,60.81 95.38,60.71 U3.F6
  BOTTOM w0.102: C1.2 109.47,60.99 R2.1 108.8,61.66 108.27,61.66 107.25,60.63 95.89,60.63 95.48,61.04 v1(95.48,61.21)
N65361: length 10
  TOP w0.152: U3.U20 v1(83.69,46.25)
  ART2 w0.152: v2(86.16,38.86) 83.64,41.38 83.64,46.2 v1(83.69,46.25)
  BOTTOM w0.203: v2(86.16,38.86) 86.16,38 R4.2
N65373: length 25.2
  TOP w0.152: v1(97.69,47.17) 97.69,47.17 U3.D19
  BOTTOM w0.152: R8.1 R6.2 109.14,34.24 100.51,42.88 99.44,42.88 97.69,44.63 v1(97.69,47.17)
N71766: length 37.2
  TOP w0.152: R127.2 v2(109.98,88.75) ; U3.L4 90.15,62.72 v1(90.63,63.2)
  ART2 w0.152: v1(90.63,63.2) 90.63,63.22 91.26,63.86 91.26,68.94 92.35,70.03 92.35,74.37 103.68,85.7 106.93,85.7 v2(109.98,88.75)
N72632: length 41.2
  TOP w0.152: v1(92.66,63.17) 92.2,62.71 U3.J4 ; R141.1 118.85,88.8 v2(118.77,88.72)
  ART2 w0.152: v2(118.77,88.72) 110.08,80.04 105.03,80.04 93.48,68.49 93.48,65.03 93.19,64.74 93.19,63.73 92.66,63.2 v1(92.66,63.17)
N73220: length 32.6
  TOP w0.152: v1(89.64,64.21) 89.15,63.73 U3.M3 ; R119.2 v2(104.9,88.82)
  BOTTOM w0.152: v1(89.64,64.21) 90.14,64.72 90.14,72.64 104.9,87.4 v2(104.9,88.82)
N73812: length 69.7
  TOP w0.152: v2(74.47,60.86) 75.95,60.86 77.62,59.18 79.68,59.18 U3.AA8
  ART2 w0.152: v2(74.47,60.86) 64.06,60.86 60.55,64.36 55.04,64.36 34.44,84.96 28.12,84.96 24.64,88.44 v2(24.64,88.47)
  BOTTOM w0.152: R86.1 v2(24.64,88.47)
N179918: length 3.5
  TOP w0.305: U16.16 23.65,62.47 R163.2 R165.1
N180887: length 3.4
  TOP w0.305: R172.1 R170.2 26.11,43.02 U19.16
N181938: length 3.8
  TOP w0.305: R181.2 13.69,19.98 14.08,19.59 U20.16
  TOP w0.381: R181.2 R183.1
N182899: length 3.5
  TOP w0.305: U17.16 11.38,63.05 R164.2 R166.1
N183888: length 3
  TOP w0.305: U18.16 19.68,31.79 R171.2 R173.1
N606190: length 8.3
  BOTTOM w0.203: C4.2 92.06,33.55 U1.4
  BOTTOM w0.508: L1.2 C3.2
  BOTTOM w1.016: L1.2 90.35,34.66 U1.4
N606320: length 3
  BOTTOM w0.203: R4.1 86.39,36.25 U1.3
N607489: length 1.9
  BOTTOM w0.152: U2.4 99.75,30.61 R9.1
N607623: length 21.3
  TOP w0.152: R5.1 100.79,9.63 SW1.2
  BOTTOM w0.152: U2.1 100.89,25.6 100.89,9.68 SW1.2
N607665: length 3.8
  BOTTOM w0.152: R10.2 R8.2 107.57,28.04 U2.7
N1798468: length 3.6
  TOP w0.305: U16.9 v3(22.77,56.47)
  BOTTOM w0.305: R167.1 22.77,58.38 v3(22.77,56.47)
N1808198: length 3.2
  TOP w0.305: U19.9 25.47,37.51 v3(25.25,37.29)
  BOTTOM w0.305: R174.1 25.25,38.71 v3(25.25,37.29)
N1818788: length 3.4
  TOP w0.203: U20.9 13.43,13.68 v2(13.67,13.44)
  BOTTOM w0.203: R186.1 13.67,15.09 v2(13.67,13.44)
N1828438: length 3.5
  TOP w0.305: U17.9 v3(10.73,55.82)
  BOTTOM w0.305: R168.1 10.73,58.28 v3(10.73,55.82)
N1838328: length 3.7
  TOP w0.305: U18.9 v3(19.12,25.92)
  BOTTOM w0.305: R175.1 19.12,27.42 v3(19.12,25.92)
N15089767: length 2.4
  BOTTOM w0.152: O1.1 R3.1
N15104211: length 2.8
  TOP w0.152: J8.3 60.17,61.62 R42.2
N15135333: length 1.9
  TOP w0.203: D1.2 R11.2
N15135363: length 1.9
  TOP w0.203: D2.2 R12.2
N15135433: length 1.9
  TOP w0.203: D3.2 R13.2
N15135465: length 1.9
  TOP w0.203: D4.2 R14.2
N15135513: length 1.9
  TOP w0.203: D5.2 R15.2
N15135593: length 1.9
  TOP w0.203: D6.2 R16.2
N15135681: length 1.9
  TOP w0.203: D7.2 R17.2
N15135745: length 1.9
  TOP w0.203: D8.2 R18.2
N15136939: length 4.9
  BOTTOM w0.152: R23.1 J2.1 144.53,79.22 R21.1
N15136999: length 34.6
  TOP w0.152: v2(116.66,56.46) 115.75,56.46 U4.3
  BOTTOM w0.152: R21.2 140.54,78.73 118.28,56.46 v2(116.66,56.46)
N15137097: length 3.8
  TOP w0.152: R25.1 R24.1 112.47,57.15 U4.4
N15137609: length 8.4
  TOP w0.152: R19.1 145.72,20.27 J1.1
  BOTTOM w0.152: R20.1 145.8,20.24 J1.1
N15137848: length 10.1
  TOP w0.152: R26.1 145.19,32.33 J3.1
  BOTTOM w0.152: R27.1 J3.1
N15138095: length 8.6
  TOP w0.152: J5.1 145.72,42.93 R30.1
  BOTTOM w0.203: J5.1 145.77,42.88 R31.1
N15138348: length 8.5
  TOP w0.152: R28.1 145.64,64.21 J4.1
  BOTTOM w0.152: R29.1 J4.1
N15138605: length 8.7
  TOP w0.152: R32.1 145.67,53.59 J6.1
  BOTTOM w0.152: J6.1 145.77,53.64 R33.1
N16764512: length 3.7
  TOP w0.305: R191.1 R190.2 8.31,81.94 U21.16
N16766730: length 1.9
  TOP w0.305: R185.2 32.94,61.19 D18.2
N16766909: length 1.9
  TOP w0.508: D19.2 R187.2
N16767511: length 2.2
  TOP w0.203: D21.2 17.4,55.93 R189.2
N16767909: length 1.8
  TOP w0.305: D17.2 30.07,30.94 R184.2
N16777633: length 3.1
  TOP w0.203: U12.5 v2(62.57,15.28)
  BOTTOM w0.203: R52.2 62.57,15.96 v2(62.57,15.28)
N16778120: length 5.4
  TOP w0.508: R62.1 J15.2 94.44,16.54 U14.1
N16778188: length 12.7
  TOP w0.203: v2(75.98,8.79) U13.2 ; v2(75.97,10.29) 75.97,9.96 75.77,9.75 71.02,9.75 69.42,11.35 69.42,11.64 69.56,11.78 U12.16
  BOTTOM w0.203: v2(75.97,10.29) 76.23,10.03 76.23,9.03 v2(75.98,8.79)
N16778190: length 14.4
  TOP w0.203: U12.15 68.92,11.78 69.06,11.64 69.06,11.21 70.87,9.4 75.91,9.4 76.8,10.29 v2(76.96,10.29) ; v2(76.98,8.79) 76.91,8.72 76.91,7.17 U13.3
  BOTTOM w0.203: v2(76.96,10.29) 76.58,9.91 76.58,9.18 v2(76.98,8.79)
N16778248: length 2.7
  TOP w0.203: U12.21 v2(72.73,14.92)
  BOTTOM w0.203: v2(72.73,14.92) 72.73,15.63 R53.2
N16778864: length 3.7
  TOP w0.203: D16.1 8.74,48.01 R194.2
N16779811: length 1.4
  BOTTOM w0.203: DR17.2 DR12.2
N16779911: length 1.4
  BOTTOM w0.203: DR14.2 DR18.2
N16782519: length 2
  TOP w0.203: D11.1 86.89,4.8 85.01,4.8 R54.1
N16783572: length 2.8
  TOP w0.152: R78.1 20.8,93.65 J16.B2
N16783577: length 2.7
  TOP w0.152: R83.1 J16.B4
N16783581: length 2.8
  TOP w0.152: J16.B6 25.88,93.65 R87.1
N16783585: length 2.8
  TOP w0.152: J16.B8 28.47,93.65 R100.1
N16783590: length 2.7
  TOP w0.152: R92.1 J16.B10
N16783594: length 2.8
  TOP w0.152: J16.B12 33.55,93.65 R104.1
N16783598: length 2.7
  TOP w0.152: R106.1 J16.B14
N16783603: length 2.7
  TOP w0.152: R111.1 J16.B16
N16783607: length 2.7
  TOP w0.152: R116.1 J16.B18
N16783611: length 2.8
  TOP w0.152: J16.B20 43.66,93.65 R120.1
N16783616: length 2.7
  TOP w0.152: R124.1 J16.B22
N16783620: length 2.7
  TOP w0.152: R128.1 J16.B24
N16783624: length 2.7
  TOP w0.152: R132.1 J16.B26
N16783629: length 2.8
  TOP w0.152: R136.1 53.82,93.65 J16.B28
N16783633: length 2.8
  TOP w0.152: R140.1 56.41,93.65 J16.B30
N16783637: length 2.7
  TOP w0.152: R144.1 J16.B32
N16783642: length 2.7
  TOP w0.152: R148.1 J16.B34
N16783646: length 2.7
  TOP w0.152: R152.1 J16.B36
N16783650: length 2.7
  TOP w0.152: R156.1 J16.B38
N16783654: length 2.7
  TOP w0.152: R160.1 J16.B40
N16789956: length 5
  TOP w0.152: J17.A3 v1(85.85,95.61)
  BOTTOM w0.152: v1(85.85,95.61) 85.75,95.5 R84.2
N16789966: length 5
  TOP w0.152: J17.A7 v1(90.93,95.63)
  BOTTOM w0.152: R89.2 90.93,91.36 v1(90.93,95.63)
N16789976: length 5.1
  TOP w0.152: J17.A11 v1(96.01,95.71)
  BOTTOM w0.152: v1(96.01,95.71) R94.2
N16789981: length 5
  TOP w0.152: J17.A13 v1(98.55,95.66)
  BOTTOM w0.152: R107.2 v1(98.55,95.66)
N16789986: length 5
  TOP w0.152: J17.A15 v1(101.09,95.66)
  BOTTOM w0.152: v1(101.09,95.66) R112.2
N16789991: length 5
  TOP w0.152: J17.A17 v1(103.63,95.63)
  BOTTOM w0.152: v1(103.63,95.63) R117.2
N16789996: length 5
  TOP w0.152: J17.A19 v1(106.17,95.66)
  BOTTOM w0.152: v1(106.17,95.66) R121.2
N16790001: length 5
  TOP w0.152: J17.A21 108.69,94.97 v1(108.69,95.63)
  BOTTOM w0.152: R125.2 v1(108.69,95.63)
N16790006: length 4.9
  TOP w0.152: J17.A23 v1(111.25,95.58)
  BOTTOM w0.152: v1(111.25,95.58) 111.25,91.47 R129.2
N16790016: length 5.1
  TOP w0.152: J17.A27 v1(116.33,95.66)
  BOTTOM w0.152: v1(116.33,95.66) 116.33,91.44 R137.2
N16790021: length 4.1
  TOP w0.152: R141.2 118.27,91.92 118.27,94.34 J17.A29
N16790026: length 4.1
  TOP w0.152: J17.A31 121.39,94.95 120.8,94.36 120.8,91.95 R145.2
N16790031: length 4.2
  TOP w0.152: R149.2 123.32,92 123.32,94.34 123.93,94.95 J17.A33
N16790036: length 4.1
  TOP w0.152: J17.A35 125.86,94.31 125.86,91.97 R153.2
N16790041: length 4
  TOP w0.152: R157.2 129.67,91.59 129.67,94.26 129.03,94.89 J17.A37
N16790052: length 4.2
  TOP w0.152: R161.2 132.21,92 132.21,94.34 131.6,94.95 J17.A39
N16790060: length 2.4
  TOP w0.152: R81.1 84.58,91.44 J17.B2
N16790070: length 2.4
  TOP w0.152: J17.B6 89.66,91.52 R88.1
N16790080: length 2.3
  TOP w0.152: R93.1 94.74,91.36 J17.B10
N16790085: length 2.3
  TOP w0.152: J17.B12 R105.1
N16790090: length 2.3
  TOP w0.152: J17.B14 R110.1
N16790095: length 2.3
  TOP w0.152: R114.1 J17.B16
N16790100: length 2.3
  TOP w0.152: R119.1 J17.B18
N16790105: length 2.3
  TOP w0.152: R123.1 J17.B20
N16790110: length 2.3
  TOP w0.152: J17.B22 R127.1
N16790120: length 2.3
  TOP w0.152: J17.B26 R135.1
N16790130: length 2.3
  TOP w0.152: J17.B30 v1(120.14,92.56)
  BOTTOM w0.152: v1(120.14,92.56) R143.1
N16790135: length 2.3
  TOP w0.152: J17.B32 v1(122.68,92.84)
  BOTTOM w0.152: v1(122.68,92.84) 122.68,91.36 R147.1
N16790140: length 2.3
  TOP w0.152: J17.B34 v1(125.22,92.81)
  BOTTOM w0.152: v1(125.22,92.81) R151.1
N16790145: length 2.3
  TOP w0.152: J17.B36 v1(127.76,92.79)
  BOTTOM w0.152: v1(127.76,92.79) R155.1
N16790150: length 2.3
  TOP w0.152: J17.B38 v1(130.3,92.76)
  BOTTOM w0.152: v1(130.3,92.76) 130.3,91.36 R159.1
N16790155: length 2.3
  TOP w0.152: J17.B40 v1(132.84,92.79)
  BOTTOM w0.152: v1(132.84,92.79) 132.84,91.36 R162.1
N16838243: length 4.9
  TOP w0.152: J17.A4 v1(87.12,95.61)
  BOTTOM w0.152: R97.2 87.12,91.36 v1(87.12,95.61)
N16838862: length 2.3
  TOP w0.152: J17.B5 88.39,91.36 R98.1
N16839386: length 5.1
  TOP w0.152: J17.A8 92.2,95.63 v1(92.18,95.66)
  BOTTOM w0.152: v1(92.18,95.66) 92.18,91.47 R101.2
N16839910: length 2.4
  TOP w0.152: J17.B9 93.47,91.57 R102.1
N16840818: length 5
  TOP w0.152: J17.A26 v1(115.06,95.63)
  BOTTOM w0.152: R139.2 115.06,91.49 v1(115.06,95.63)
N16841427: length 2.4
  TOP w0.152: J17.B25 113.79,91.49 R133.1
N16841941: length 4.9
  TOP w0.152: J17.A24 v1(112.52,95.61)
  BOTTOM w0.152: v1(112.52,95.61) R131.2
N17984614: length 1.8
  TOP w0.305: C140.1 24.48,61.19 U16.15
N18081914: length 1.6
  TOP w0.305: U19.15 27.17,41.96 C148.1
N18187814: length 1.5
  TOP w0.381: U20.15 15.13,17.98 C157.1
N18284314: length 2
  TOP w0.305: C141.1 12.44,60.48 U17.15
N18383214: length 1.6
  TOP w0.305: C149.1 20.82,30.66 U18.15
N151370452: length 1.7
  TOP w0.152: U4.1 R22.1
N167617330: length 3.3
  BOTTOM w1.016: R178.1 J18.1
N167617332: length 3.1
  BOTTOM w1.016: R179.1 J18.3
N167644448: length 3.9
  TOP w0.305: v2(7.65,74.17) 7.65,74.35 7.66,74.36 U21.9
  BOTTOM w0.305: v2(7.65,74.17) 7.65,76.48 R192.1
N167671021: length 1.8
  TOP w0.305: R188.2 D20.2
N167776730: length 2.2
  TOP w0.203: U12.38 71.48,22.82 R55.1
N167776810: length 2.7
  TOP w0.203: R58.1 68.92,24.24 U12.42
N167776910: length 2.5
  TOP w0.203: v2(65.13,14.07) 65.13,12.92 U12.9
  BOTTOM w0.203: R59.1 v2(65.13,14.07)
N167800060: length 1.9
  TOP w0.152: D12.2 DR9.1
N167800300: length 1.9
  TOP w0.152: DR10.1 D13.2
N167800460: length 1.6
  TOP w0.152: DR11.1 114.22,41.35 D14.2
N167801340: length 3.5
  BOTTOM w0.203: DR7.1 124.18,43 125.32,41.86
N167801341: length 1.9
  BOTTOM w0.203: 134.92,41.86 134.65,41.58 DR8.1
N167815100: length 9.8
  TOP w0.203: U13.1 75.18,6.02 75.87,5.33 79.45,5.33 79.93,4.85 R54.2
N167837560: length 4.8
  TOP w0.152: J16.A1 v2(19.56,95.76)
  BOTTOM w0.152: v2(19.56,95.76) R77.2
N167837562: length 4.8
  TOP w0.152: J16.A3 v2(22.1,95.78)
  BOTTOM w0.152: R80.2 22.1,91.82 v2(22.1,95.78)
N167837564: length 4.8
  TOP w0.152: J16.A5 v2(24.64,95.78)
  BOTTOM w0.152: v2(24.64,95.78) R86.2
N167837566: length 4.8
  TOP w0.152: J16.A7 v2(27.18,95.78)
  BOTTOM w0.152: v2(27.18,95.78) R99.2
N167837568: length 4.8
  TOP w0.152: J16.A9 v2(29.72,95.78)
  BOTTOM w0.152: v2(29.72,95.78) R91.2
N168028960: length 1.5
  TOP w0.203: J13.1 63.14,31.72 R60.1
N168030100: length 1.6
  TOP w0.203: J14.1 68.28,31.83 R61.1
N1676444414: length 1.9
  TOP w0.305: U21.15 v3(10.33,78.87)
  BOTTOM w0.305: v3(10.33,78.87) 11.17,78.87 C161.1
N1678375610: length 4.8
  TOP w0.152: J16.A11 v2(32.26,95.78)
  BOTTOM w0.152: v2(32.26,95.78) R103.2
N1678375612: length 4.7
  TOP w0.152: J16.A13 v2(34.8,95.73)
  BOTTOM w0.152: v2(34.8,95.73) R96.2
N1678375614: length 4.9
  TOP w0.152: J16.A15 v2(37.34,95.81)
  BOTTOM w0.152: R109.2 37.34,91.82 v2(37.34,95.81)
N1678375616: length 4.7
  TOP w0.152: J16.A17 v2(39.88,95.71)
  BOTTOM w0.152: v2(39.88,95.71) R113.2
N1678375618: length 4.9
  TOP w0.152: J16.A19 v2(42.42,95.81)
  BOTTOM w0.152: v2(42.42,95.81) R118.2
N1678375620: length 4.8
  TOP w0.152: J16.A21 v2(44.96,95.78)
  BOTTOM w0.152: v2(44.96,95.78) R122.2
N1678375622: length 4.8
  TOP w0.152: J16.A23 v2(47.5,95.76)
  BOTTOM w0.152: v2(47.5,95.76) R126.2
N1678375624: length 4.8
  TOP w0.152: J16.A25 v2(50.04,95.78)
  BOTTOM w0.152: v2(50.04,95.78) R130.2
N1678375626: length 4.9
  TOP w0.152: J16.A27 v2(52.58,95.81)
  BOTTOM w0.152: v2(52.58,95.81) R134.2
N1678375628: length 4.7
  TOP w0.152: J16.A29 v2(55.12,95.7)
  BOTTOM w0.152: v2(55.12,95.7) R138.2
N1678375630: length 1.7
  TOP w0.102: J16.A31 v1(57.66,95.78)
  BOTTOM w0.102: v1(57.66,95.78) R142.2
N1678375632: length 4.9
  TOP w0.152: J16.A33 v2(60.2,95.83)
  BOTTOM w0.152: v2(60.2,95.83) R146.2
N1678375634: length 5
  TOP w0.152: J16.A35 v2(62.74,95.81)
  BOTTOM w0.152: v2(62.74,95.81) R150.2
N1678375636: length 5
  TOP w0.152: J16.A37 v2(65.28,95.81)
  BOTTOM w0.152: v2(65.28,95.81) R154.2
N1678375638: length 5
  TOP w0.152: J16.A39 v2(67.82,95.81)
  BOTTOM w0.152: v2(67.82,95.81) R158.2
N1679025740: length 2.4
  TOP w0.152: J17.B1 83.31,91.44 R79.1

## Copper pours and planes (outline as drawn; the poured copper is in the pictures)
1.0V on TOP: 11.56,35.48 11.56,32.03 15.47,32.03 15.47,35.48
1.0V on PLANE7: 12.5,24.71 12.5,39.65 83.95,39.65 83.95,52.27 94.74,52.27 94.74,55.5 87.02,55.5 87.02,56.85 82.25,56.85 82.25,63.68 97.84,63.68 97.84,55.32 100.99,55.32 100.99,60.96 103.2,60.96 103.2,63.68 106.65,63.68 106.65,24.71 80.04,24.71 80.04,25.37 58.47,25.37 58.47,24.71
1.0V_OUT on TOP: 11.71,29.26 11.71,31.93 15.98,31.93 15.98,35.51 18.82,35.51 18.82,31.01 17.02,31.01 17.02,29.26
1.2V on TOP: 4.17,67.79 4.17,60.6 6.1,60.6 6.1,67.79
1.2V on PLANE7: 98.35,55.83 98.35,64.19 81.74,64.19 81.74,56.82 1.52,56.82 1.52,71.37 106.63,71.37 106.63,64.19 102.69,64.19 102.69,61.09 100.48,61.09 100.48,55.83
1.2V_OUT on TOP: 6.71,59.79 6.71,67.54 13.08,67.54 13.08,62.59 11.86,62.59 11.86,60.91 13.08,60.91 13.08,59.79
1.8V on TOP: 4.04,23.93 4.04,20.5 9.6,20.5 9.6,23.93
1.8V on PLANE7: 1.52,1.52 1.52,56.31 86.51,56.31 86.51,54.99 94.23,54.99 94.23,52.78 83.44,52.78 83.44,40.16 11.99,40.16 11.99,24.21 17.2,24.21 17.2,1.52
1.8V_OUT on TOP: 4.06,16.54 4.06,19.99 10.11,19.99 10.11,23.62 12.78,23.62 12.78,18.44 11.56,18.44 11.56,16.54
2.5V on PLANE3: 17.73,34.49 17.73,48.59 74.55,48.59 74.55,66.85 105.59,66.88 105.59,34.49
3.3V on TOP: 39.65,18.44 39.65,16.15 42.77,16.15 42.77,18.44
3.3V on TOP: 16.1,68.5 16.1,63.14 19.66,63.14 19.66,68.5
3.3V on TOP: 71.22,21.69 71.22,20.02 69.82,20.02 69.82,21.69
3.3V on TOP: 95.81,16.74 95.81,18.06 93.95,18.06 93.95,23.01 97,23.01 97,18.54 98.98,18.54 98.98,16.74
3.3V on TOP: 73.58,21.51 73.58,19.33 74.78,19.33 74.78,21.51
3.3V on TOP: 55.52,13.31 55.52,9.83 57.68,9.83 57.68,13.31
3.3V on TOP: 87.45,23.62 87.45,20.7 90.17,20.7 90.17,23.62
3.3V on TOP: 47.24,22.83 47.24,19.79 49.3,19.79 49.3,22.83
3.3V on TOP: 30.51,22.38 30.51,21.08 32.11,21.08 32.11,22.38
3.3V on TOP: 38.3,27.2 38.3,25.27 33.1,25.27 33.1,27.2
3.3V on BOTTOM: 95.35,29.06 95.35,24.79 100.08,24.79 100.08,29.06
3.3V on BOTTOM: 42.39,19.53 42.39,15.93 45.19,15.93 45.19,19.53
3.3V on BOTTOM: 129.87,52.12 129.87,52.32 126.8,52.32 126.8,58.45 130.53,58.45 130.53,53.01 132.79,53.01 132.79,52.12
3.3V on BOTTOM: 137.77,57.43 137.77,53.44 141.81,53.44 141.81,57.43
3.3V on BOTTOM: 28.96,24.82 28.96,20.17 31.45,20.17 31.45,24.82
3.3V on BOTTOM: 69.52,19.81 69.52,22.76 75.67,22.76 75.67,19.81
3.3V on BOTTOM: 87.43,31.01 87.43,37.69 89.31,37.69 89.31,31.01
3.3V on BOTTOM: 116.87,69.6 116.87,64.24 124.92,64.24 124.92,69.6
3.3V on BOTTOM: 52.27,23.52 52.27,19.53 54.74,19.53 54.74,23.52
3.3V on PLANE5: 1.52,1.52 1.52,10.16 30.68,10.16 30.68,16.79 24.31,16.79 24.31,26.54 30.68,26.54 30.68,60.99 1.52,60.99 1.52,73.58 150.88,73.58 150.88,1.52
